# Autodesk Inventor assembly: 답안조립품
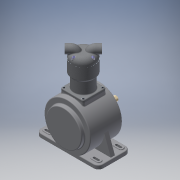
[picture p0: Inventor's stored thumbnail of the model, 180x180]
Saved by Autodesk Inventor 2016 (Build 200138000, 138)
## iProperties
Created: 2015-06
Part Number: 답안조립품
Document SubType Name: Assembly
Designer: Administrator
Author: Administrator
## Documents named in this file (15)
- C:\Users\Administrator\Desktop\450606V1033\답안조립품.iam
- C:\Users\Administrator\Desktop\450606V1033\본체.ipt
- C:\Users\Administrator\Desktop\450606V1033\크랭크 서브축.ipt
- C:\Users\Administrator\Desktop\450606V1033\메인 크랭크 축-구동부.ipt
- C:\Users\Administrator\Desktop\450606V1033\커넥팅 로드.ipt
- C:\Users\Administrator\Desktop\450606V1033\베어링 NA 4902.ipt
- C:\Users\Administrator\Desktop\450606V1033\베어링 6204.ipt
- C:\Users\Administrator\Desktop\450606V1033\메인커버.ipt
- C:\Users\Administrator\Desktop\450606V1033\오일실.ipt
- C:\Users\Administrator\Desktop\450606V1033\실린더.ipt
- C:\Users\Administrator\Desktop\450606V1033\피스톤.ipt
- C:\Users\Administrator\Desktop\450606V1033\피스톤 핀.ipt
- C:\Users\Administrator\Desktop\450606V1033\실린더헤드.ipt
- C:\Users\Administrator\Desktop\450606V1033\M5x0.8.ipt
- C:\Users\Administrator\Desktop\450606V1033\M4x0.7.ipt
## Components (14 placed, 4 different names)
1. 피스톤:1
2. 피스톤 핀:1
3. M4x0.7:1
4. M4x0.7:2
5. M4x0.7:3
6. M4x0.7:4
7. M5x0.8:1
8. M5x0.8:2
9. M5x0.8:3
10. M5x0.8:4
11. M4x0.7:5
12. M4x0.7:6
13. M4x0.7:7
14. M4x0.7:8
